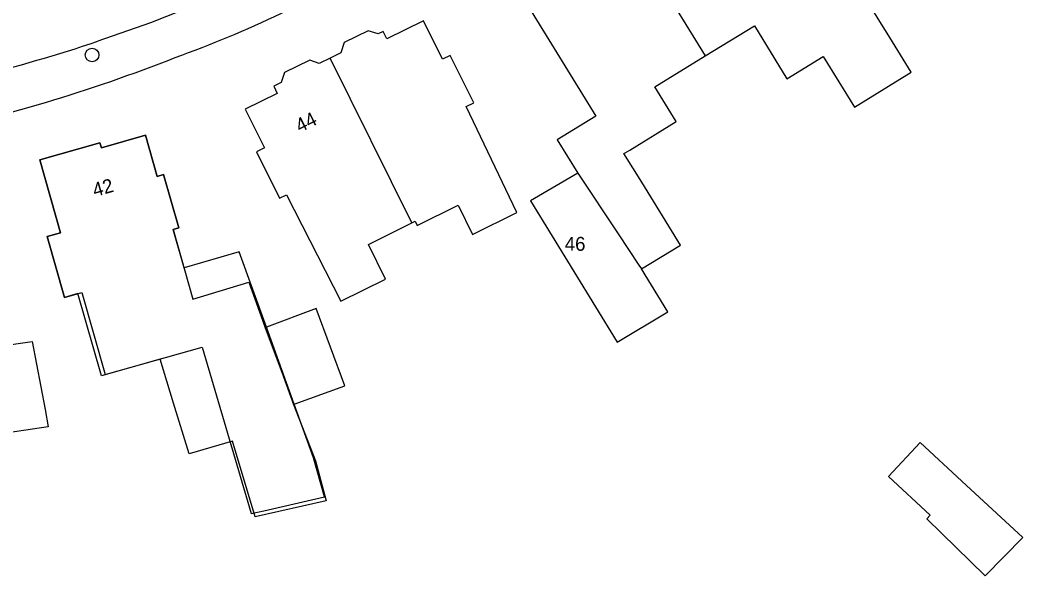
# Model space of a CAD drawing. Extents: x 161354 to 161876, y 382161 to 382804.
# Drawn here: x 161596.3 to 161668.5, y 382231.6 to 382271.6 of the extents above; entities that cross this region are included whole.
import ezdxf

# ---------------------------------------------------------------- set-up
doc = ezdxf.new("R2010")
doc.units = 0
for name, color, linetype in [('IMGEO_Boom', 7, 'Continuous'), ('IMGEO_Pand', 7, 'Continuous'), ('IMGEO_Pand_nummerreeks', 7, 'Continuous'), ('IMGEO_Pand_vergunning_verleend', 7, 'Continuous'), ('IMGEO_Rijbaan_lokaal_open', 7, 'Continuous'), ('IMGEO_Voetpad_open', 7, 'Continuous')]:
    doc.layers.add(name, color=color, linetype=linetype)

msp = doc.modelspace()

# ---------------------------------------------------------------- linework, layer by layer
at = {"layer": 'IMGEO_Boom'}
msp.add_circle((161601.505, 382269.102), 0.489, dxfattribs=at)
at = {"layer": 'IMGEO_Pand'}
for points in [[(161645.623, 382269.03), (161649.162, 382271.205), (161651.508, 382267.386), (161654.12, 382269.001), (161656.377, 382265.35), (161660.453, 382267.871), (161658.721, 382270.672), (161658.197, 382271.524), (161655.579, 382275.783), (161654.477, 382277.536), (161651.7, 382275.829), (161647.731, 382282.286), (161646.932, 382281.795), (161646.693, 382282.184), (161646.127, 382281.836), (161644.704, 382284.152), (161641.895, 382282.426), (161641.317, 382283.367), (161638.045, 382281.357)], [(161638.045, 382281.357), (161634.538, 382279.202), (161635.132, 382278.235), (161632.231, 382276.452), (161633.687, 382274.081), (161633.155, 382273.753), (161633.427, 382273.31), (161632.722, 382272.877), (161637.748, 382264.697), (161634.981, 382262.997), (161636.457, 382260.596)], [(161638.045, 382281.357), (161645.623, 382269.03)], [(161624.511, 382257.002), (161624.753, 382257.122), (161624.901, 382256.822), (161627.836, 382258.273), (161628.876, 382256.17), (161632.076, 382257.752), (161628.434, 382265.387), (161628.965, 382265.65), (161627.272, 382269.073), (161626.714, 382268.796), (161625.345, 382271.563), (161622.726, 382270.268), (161622.462, 382270.803), (161622.081, 382270.615), (161621.379, 382270.852), (161619.647, 382269.995), (161619.4, 382269.266), (161618.625, 382268.882)], [(161641.033, 382253.694), (161643.843, 382255.393), (161641.053, 382259.934), (161639.781, 382262.004), (161639.874, 382262.061), (161640.191, 382262.256), (161643.529, 382264.307), (161641.996, 382266.802), (161645.623, 382269.03)], [(161618.625, 382268.882), (161617.852, 382268.5), (161617.172, 382268.73), (161615.358, 382267.833), (161615.118, 382267.124), (161614.572, 382266.854), (161614.828, 382266.336), (161612.528, 382265.198), (161613.902, 382262.42), (161613.324, 382262.134), (161614.982, 382258.782), (161615.494, 382259.035), (161619.399, 382251.373), (161622.617, 382252.966), (161621.386, 382255.456), (161624.511, 382257.002)], [(161624.511, 382257.002), (161618.625, 382268.882)], [(161614.045, 382249.488), (161612.081, 382254.919), (161608.119, 382253.767), (161607.331, 382256.532), (161607.742, 382256.649), (161606.65, 382260.485), (161606.198, 382260.356), (161605.355, 382263.317), (161602.175, 382262.412), (161602.072, 382262.772), (161597.745, 382261.54), (161599.239, 382256.294), (161598.278, 382256.02), (161599.525, 382251.645), (161600.76, 382251.997), (161602.445, 382246.079), (161609.426, 382248.067), (161612.952, 382236.065), (161613.868, 382236.274), (161618.229, 382237.27), (161617.443, 382240.091), (161616.046, 382243.956)], [(161636.457, 382260.596), (161633.057, 382258.588), (161639.3, 382248.425), (161642.926, 382250.613), (161641.033, 382253.694)], [(161636.457, 382260.596), (161639.362, 382256.214), (161640.853, 382253.965), (161641.033, 382253.694)], [(161583.448, 382258.278), (161586.606, 382258.752), (161587.153, 382258.065), (161590.924, 382258.63), (161591.363, 382255.702), (161592.22, 382255.831), (161592.818, 382251.842), (161591.92, 382251.707), (161592.177, 382250), (161592.287, 382249.269), (161594.453, 382249.595), (161594.678, 382248.098), (161597.2, 382248.477), (161598.115, 382243.562), (161598.345, 382242.329), (161594.283, 382241.72), (161593.99, 382243.668), (161589.507, 382242.995), (161589.187, 382245.123), (161585.465, 382244.564)], [(161616.046, 382243.956), (161619.691, 382245.273), (161617.62, 382250.853), (161614.045, 382249.488)], [(161616.046, 382243.956), (161614.045, 382249.488)], [(161664.103, 382238.409), (161661.1, 382241.201), (161658.81, 382238.737), (161661.812, 382235.945), (161661.574, 382235.689), (161665.761, 382231.578), (161668.49, 382234.358), (161664.103, 382238.409)]]:
    msp.add_lwpolyline(points, dxfattribs=at)
at = {"layer": 'IMGEO_Pand_vergunning_verleend'}
msp.add_lwpolyline([(161597.745, 382261.54), (161602.072, 382262.772), (161602.175, 382262.412), (161605.355, 382263.317), (161606.198, 382260.356), (161606.65, 382260.485), (161607.742, 382256.649), (161607.331, 382256.532), (161608.761, 382251.512), (161612.782, 382252.741), (161613.772, 382250), (161613.97, 382249.459), (161615.147, 382246.248), (161615.994, 382243.937), (161617.578, 382239.875), (161618.343, 382236.984), (161613.233, 382235.848), (161611.609, 382241.295), (161608.49, 382240.369), (161607.363, 382244.016), (161606.394, 382247.186), (161602.177, 382245.985), (161601.034, 382250), (161600.487, 382251.919), (161599.525, 382251.645), (161598.278, 382256.02), (161599.239, 382256.294), (161597.745, 382261.54)], dxfattribs=at)
at = {"layer": 'IMGEO_Rijbaan_lokaal_open'}
msp.add_lwpolyline([(161609.273, 382272.828), (161605.711, 382271.429), (161601.914, 382270.088)], dxfattribs=at)
msp.add_arc((161565.149, 382379.907), 115.809, 283.96622, 288.50925, dxfattribs=at)
at = {"layer": 'IMGEO_Voetpad_open'}
for centre, radius, start, end in [((161578.493, 382349.06), 85.227, 289.88576, 300.97211), ((161564.574, 382378.018), 117.238, 281.81391, 291.46888)]:
    msp.add_arc(centre, radius, start, end, dxfattribs=at)

# ---------------------------------------------------------------- texts
at = {"layer": 'IMGEO_Pand_nummerreeks'}
for s, rotation, p in [('44', 26.40928, (161616.45, 382263.485)), ('42', 15.88812, (161601.701, 382258.866))]:
    msp.add_text(s, height=1, rotation=rotation, dxfattribs=at).set_placement(p)
msp.add_text('46', height=1, dxfattribs=at).set_placement((161635.52, 382254.999))

doc.saveas('drawing.dxf')
